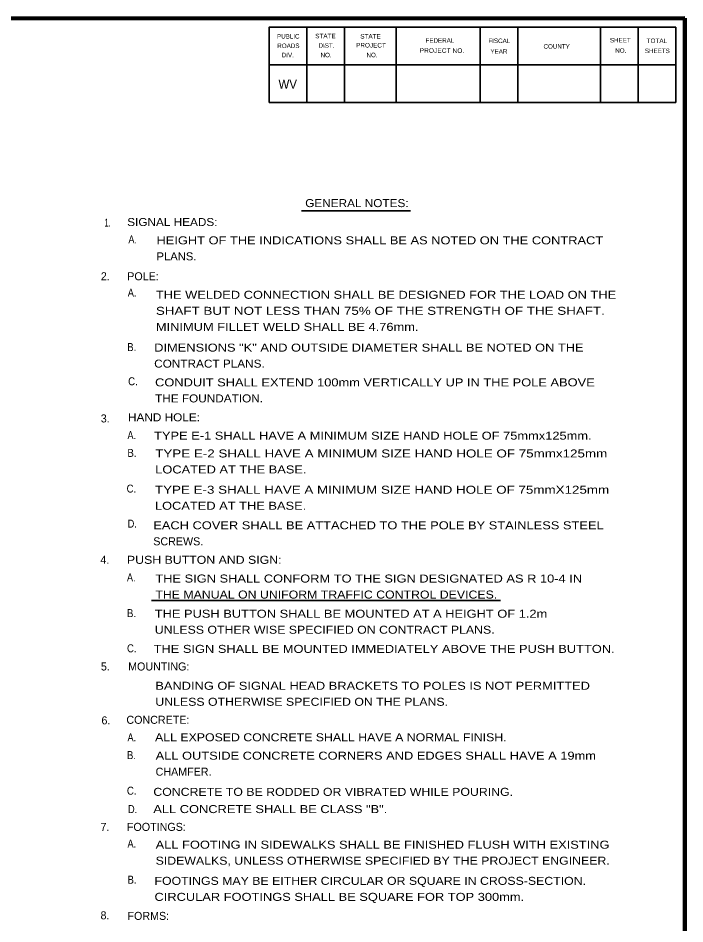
# Model space of a CAD drawing. Extents: x -761 to 95, y 34 to 578.
# Drawn here: x -136.8 to 88.1, y 266.6 to 571.9 of the extents above; entities that cross this region are included whole.
import ezdxf
from ezdxf.enums import TextEntityAlignment as Align

# ---------------------------------------------------------------- set-up
doc = ezdxf.new("R2010")
doc.units = 0
doc.header["$LTSCALE"] = 0.96
doc.layers.add('1', color=7, linetype='Continuous', lineweight=53)
doc.layers.add('61', color=7, linetype='Continuous', lineweight=35)

msp = doc.modelspace()

# ---------------------------------------------------------------- linework, layer by layer
at = {"layer": '1', "lineweight": 158}
msp.add_line((88.1275, 45.8431), (88.1275, 571.9431), dxfattribs=at)
at = {"layer": '1', "lineweight": 13}
msp.add_line((88.1275, 45.8431), (88.1275, 571.9431), dxfattribs=at)
at = {"layer": '1', "lineweight": 35}
for p, q in [((-41.2497, 507.0198), (-4.424, 507.0198)), ((-91.8587, 375.5406), (25.964, 375.5406))]:
    msp.add_line(p, q, dxfattribs=at)
at = {"layer": '1', "lineweight": 158}
msp.add_lwpolyline([(88.1275, 571.9431), (-703.5725, 571.8431), (-703.4725, 45.8431)], dxfattribs=at)
at = {"layer": '61'}
for p, q in [((-39.3725, 568.9431), (-39.3725, 543.5431)), ((-26.6725, 568.9431), (-26.6725, 543.5431)), ((-9.2725, 568.9431), (-9.2725, 543.5431)), ((19.0275, 568.9431), (19.0275, 543.5431)), ((31.7275, 568.9431), (31.7275, 543.5431)), ((59.6275, 568.9431), (59.6275, 543.5431)), ((72.3275, 568.9431), (72.3275, 543.5431)), ((85.0275, 556.2431), (-52.0725, 556.2431))]:
    msp.add_line(p, q, dxfattribs=at)
for points in [[(85.0275, 568.9431), (-52.0725, 568.9431), (-52.0725, 543.5431)], [(85.0275, 568.9431), (85.0275, 543.5431), (-52.0725, 543.5431)]]:
    msp.add_lwpolyline(points, dxfattribs=at)

# ---------------------------------------------------------------- texts
at = {"layer": '1'}
for s, height, width, p in [('WV', 3.048, 0.95, (-48.9725, 548.1431)), ('1.', 2.7, 0.65, (-107.6636, 501.6254)), ('SIGNAL HEADS:', 2.7, 1.1, (-100.0005, 501.8382)), ('A.', 2.7, 0.85, (-99.6027, 495.9791)), ('HEIGHT OF THE INDICATIONS SHALL BE AS NOTED ON THE CONTRACT', 2.7, 1.2, (-90.1304, 495.6644)), ('PLANS.', 2.7, 1.05, (-90.1304, 490.2644)), ('A.', 2.7, 0.85, (-99.8035, 478.0616)), ('THE WELDED CONNECTION SHALL BE DESIGNED FOR THE LOAD ON THE', 2.7, 1.2, (-90.3325, 477.304)), ('SHAFT BUT NOT LESS THAN 75% OF THE STRENGTH OF THE SHAFT.', 2.7, 1.25, (-90.3325, 471.904)), ('MINIMUM FILLET WELD SHALL BE 4.76mm.', 2.7, 1.2, (-90.3325, 466.504)), ('B.', 2.7, 0.9, (-99.993, 459.6884)), ('DIMENSIONS "K" AND OUTSIDE DIAMETER SHALL BE NOTED ON THE', 2.7, 1.2, (-90.9007, 459.499)), ('CONTRACT PLANS.', 2.7, 1.1, (-90.9007, 454.099)), ('C.', 2.7, 0.9, (-99.6948, 448.1463)), ('CONDUIT SHALL EXTEND 100mm VERTICALLY UP IN THE POLE ABOVE', 2.7, 1.2, (-90.6022, 447.7752)), ('THE FOUNDATION.', 2.7, 1.1, (-90.6022, 442.3752)), ('HAND HOLE:', 2.7, 1.1, (-99.7367, 435.9991)), ('A.', 2.7, 0.85, (-99.9242, 430.0006)), ('TYPE E-1 SHALL HAVE A MINIMUM SIZE HAND HOLE OF 75mmx125mm.', 2.7, 1.2, (-90.9264, 429.8131)), ('B.', 2.7, 0.9, (-99.9241, 424.0021)), ('TYPE E-2 SHALL HAVE A MINIMUM SIZE HAND HOLE OF 75mmx125mm', 2.7, 1.25, (-90.5515, 423.8147)), ('LOCATED AT THE BASE.', 2.7, 1.2, (-90.5515, 418.4147)), ('C.', 2.7, 0.9, (-100.2052, 411.9589)), ('TYPE E-3 SHALL HAVE A MINIMUM SIZE HAND HOLE OF 75mmX125mm', 2.7, 1.25, (-90.6451, 411.584)), ('LOCATED AT THE BASE.', 2.7, 1.2, (-90.6451, 406.184)), ('D.', 2.7, 0.85, (-99.8303, 400.1493)), ('EACH COVER SHALL BE ATTACHED TO THE POLE BY STAINLESS STEEL', 2.7, 1.2, (-91.2075, 399.587)), ('PUSH BUTTON AND SIGN:', 2.7, 1.15, (-100.0834, 387.951)), ('A.', 2.7, 0.85, (-100.0833, 382.0216)), ('THE SIGN SHALL CONFORM TO THE SIGN DESIGNATED AS R 10-4 IN', 2.7, 1.2, (-90.5199, 381.6391)), ('THE MANUAL ON UNIFORM TRAFFIC CONTROL DEVICES.', 2.7, 1.15, (-90.5199, 376.2391)), ('B.', 2.7, 0.9, (-100.0834, 369.9716)), ('THE PUSH BUTTON SHALL BE MOUNTED AT A HEIGHT OF 1.2m', 2.7, 1.2, (-90.7112, 369.7803)), ('UNLESS OTHER WISE SPECIFIED ON CONTRACT PLANS.', 2.7, 1.15, (-90.7112, 364.3803)), ('C.', 2.7, 0.9, (-100.0834, 358.1128)), ('THE SIGN SHALL BE MOUNTED IMMEDIATELY ABOVE THE PUSH BUTTON.', 2.7, 1.2, (-91.0937, 357.9215)), ('BANDING OF SIGNAL HEAD BRACKETS TO POLES IS NOT PERMITTED', 2.7, 1.2, (-90.5199, 345.4889)), ('UNLESS OTHERWISE SPECIFIED ON THE PLANS.', 2.7, 1.15, (-90.5199, 340.0889)), ('A.', 2.7, 0.85, (-99.9034, 328.1136)), ('ALL EXPOSED CONCRETE SHALL HAVE A NORMAL FINISH.', 2.7, 1.15, (-90.6101, 328.1135)), ('B.', 2.7, 0.9, (-100.097, 322.1117)), ('ALL OUTSIDE CONCRETE CORNERS AND EDGES SHALL HAVE A 19mm', 2.7, 1.2, (-90.4166, 321.9182)), ('C.', 2.7, 0.9, (-100.097, 310.108)), ('CONCRETE TO BE RODDED OR VIBRATED WHILE POURING.', 2.7, 1.15, (-91.191, 309.7208)), ('D.', 2.7, 0.85, (-99.7098, 303.9126)), ('ALL CONCRETE SHALL BE CLASS "B".', 2.7, 1.2, (-91.191, 303.9126)), ('A.', 2.7, 0.85, (-99.9034, 292.2961)), ('ALL FOOTING IN SIDEWALKS SHALL BE FINISHED FLUSH WITH EXISTING', 2.7, 1.2, (-90.4166, 291.9089)), ('SIDEWALKS, UNLESS OTHERWISE SPECIFIED BY THE PROJECT ENGINEER.', 2.7, 1.15, (-90.4166, 286.5089)), ('B.', 2.7, 0.9, (-99.9034, 280.0988)), ('FOOTINGS MAY BE EITHER CIRCULAR OR SQUARE IN CROSS-SECTION.', 2.7, 1.15, (-90.8038, 279.7116)), ('CIRCULAR FOOTINGS SHALL BE SQUARE FOR TOP 300mm.', 2.7, 1.2, (-90.8038, 274.3116))]:
    msp.add_text(s, height=height, dxfattribs=dict(at, width=width)).set_placement(p)
at = {"layer": '1', "width": 1.1}
msp.add_text('GENERAL NOTES:', height=2.7, dxfattribs=at).set_placement((-22.5176, 508.2242), align=Align.CENTER)
at = {"layer": '1'}
for s, p in [('2.', (-108.8957, 483.5549)), ('POLE:', (-99.9929, 483.5549)), ('3.', (-108.9219, 435.6242)), ('SCREWS.', (-91.2075, 394.187)), ('4.', (-109.0731, 387.951)), ('5.', (-108.8818, 351.9921)), ('MOUNTING:', (-99.7008, 351.9921)), ('6.', (-108.6905, 333.8215)), ('CONCRETE:', (-100.2746, 334.0127)), ('CHAMFER.', (-90.4166, 316.5182)), ('7.', (-109.003, 297.9107)), ('FOOTINGS:', (-100.097, 297.9107)), ('8.', (-109.003, 268.0951)), ('FORMS:', (-99.9034, 267.9015))]:
    msp.add_text(s, height=2.7, dxfattribs=at).set_placement(p)
at = {"layer": '61'}
for s, height, rotation, p in [('PUBLIC', 1.525, 0.033, (-49.4725, 565.0431)), ('FEDERAL', 1.523, 0.007, (0.6275, 563.6431)), ('FISCAL', 1.525, 359.942, (21.8275, 563.5431)), ('SHEET', 1.525, 0.059, (62.8275, 563.7431)), ('ROADS', 1.525, 0.124, (-49.3725, 561.8431)), ('DIST.', 1.525, 0.056, (-35.4725, 561.9431)), ('COUNTY', 1.523, 0.069, (40.4275, 561.6431)), ('DIV.', 1.525, 359.932, (-47.8725, 558.7431)), ('YEAR', 1.523, 0.105, (22.5275, 559.9431)), ('SHEETS', 1.523, 359.959, (74.6275, 560.1431))]:
    msp.add_text(s, height=height, rotation=rotation, dxfattribs=at).set_placement(p)
for s, rotation, width, p in [('STATE', 0.059, 1.05, (-36.5725, 565.1431)), ('STATE', 0.059, 1.05, (-21.3725, 565.0431)), ('TOTAL', 359.926, 1.05, (75.2275, 563.5431)), ('PROJECT', 359.908, 1.05, (-22.7725, 562.0431)), ('NO.', 359.852, 0.9, (-34.7725, 558.7431)), ('NO.', 0.225, 0.9, (-19.2725, 558.7431)), ('PROJECT NO.', 359.922, 1.1, (-1.3725, 560.2431)), ('NO.', 359.852, 0.9, (64.6275, 560.2431))]:
    msp.add_text(s, height=1.525, rotation=rotation, dxfattribs=dict(at, width=width)).set_placement(p)

doc.saveas('drawing.dxf')
